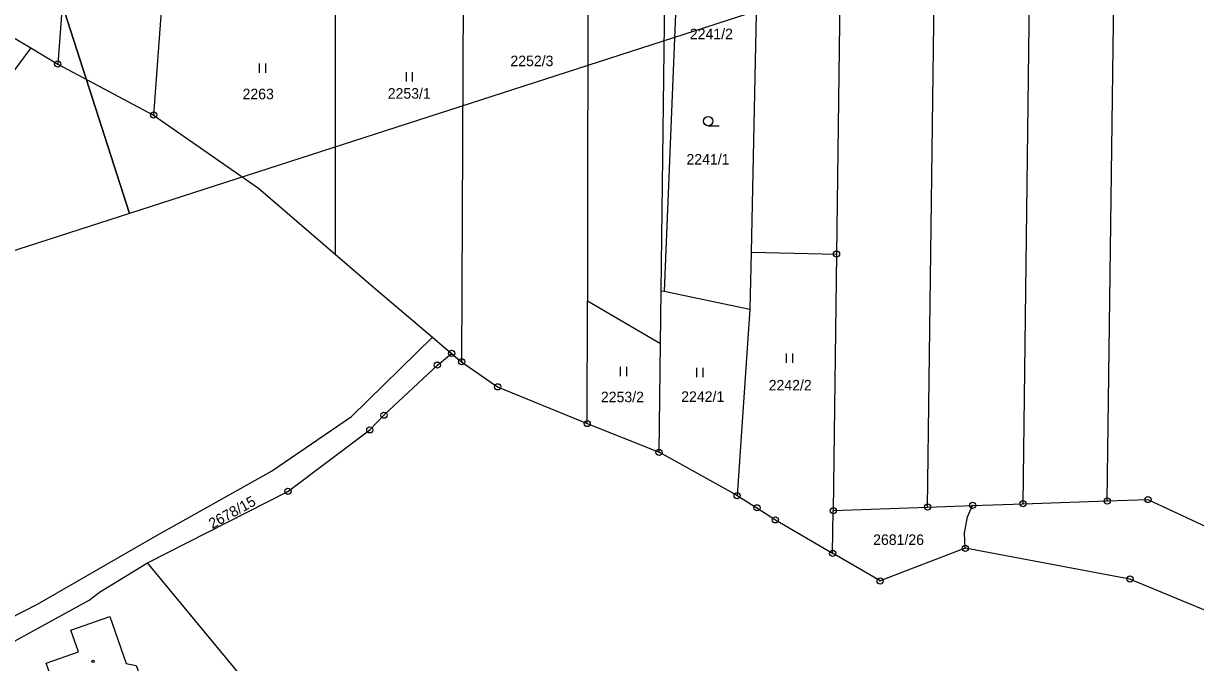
# Model space of a CAD drawing. Extents: x -758836 to -757729, y -1175316 to -1174366.
# Drawn here: x -758289.2 to -758099.9, y -1174936.9 to -1174833.7 of the extents above; entities that cross this region are included whole.
import ezdxf

# ---------------------------------------------------------------- set-up
doc = ezdxf.new("R2010")
doc.units = 0
for name, color, linetype in [('_NOR-pomocná', 7, 'Continuous'), ('Hranice parcel', 7, 'Continuous'), ('Parcelní čísla', 7, 'Continuous'), ('Značky bodu BP', 7, 'Continuous'), ('Značky budov', 7, 'Continuous'), ('Značky kultur', 7, 'Continuous')]:
    doc.layers.add(name, color=color, linetype=linetype)

msp = doc.modelspace()

# ---------------------------------------------------------------- linework, layer by layer
at = {"layer": '_NOR-pomocná'}
for points in [[(-758317.65, -1174723.03), (-758217.71, -1174690.84), (-758172.18, -1174832.19), (-758272.12, -1174864.38)], [(-758417.59, -1174755.22), (-758317.65, -1174723.03), (-758272.12, -1174864.38), (-758372.07, -1174896.57)]]:
    msp.add_lwpolyline(points, close=True, dxfattribs=at)
at = {"layer": 'Hranice parcel'}
for p, q in [((-758127.73, -1174911.25), (-758125.97, -1174774.42)), ((-758114.13, -1174910.8), (-758112.36, -1174774.1)), ((-758156.63, -1174775.13), (-758157.87, -1174870.96)), ((-758143.14, -1174911.79), (-758141.37, -1174774.78)), ((-758266.21, -1174821.26), (-758268.21, -1174848.52)), ((-758186.22, -1174876.87), (-758185.53, -1174823.65)), ((-758183.53, -1174823.59), (-758185.73, -1174876.96)), ((-758170.66, -1174823.2), (-758171.67, -1174870.63)), ((-758238.86, -1174825.45), (-758238.89, -1174870.98)), ((-758218.18, -1174826.63), (-758218.45, -1174888.34)), ((-758288.06, -1174837.68), (-758283.71, -1174840.27)), ((-758283.71, -1174840.27), (-758268.21, -1174848.52)), ((-758171.67, -1174870.63), (-758171.87, -1174879.84)), ((-758171.67, -1174870.63), (-758157.87, -1174870.96)), ((-758157.87, -1174870.96), (-758158.4, -1174912.36)), ((-758198.15, -1174898.31), (-758198.12, -1174878.49)), ((-758198.12, -1174878.49), (-758186.32, -1174885.38)), ((-758186.32, -1174885.38), (-758186.22, -1174876.87)), ((-758186.22, -1174876.87), (-758185.73, -1174876.96)), ((-758185.73, -1174876.96), (-758171.87, -1174879.84)), ((-758171.87, -1174879.84), (-758173.93, -1174909.94)), ((-758223.14, -1174884.37), (-758220.06, -1174886.98)), ((-758186.55, -1174902.95), (-758186.32, -1174885.38)), ((-758220.06, -1174886.98), (-758218.45, -1174888.34)), ((-758198.15, -1174898.31), (-758186.55, -1174902.95)), ((-758173.93, -1174909.94), (-758186.55, -1174902.95)), ((-758127.73, -1174911.25), (-758114.13, -1174910.8)), ((-758158.49, -1174919.25), (-758158.4, -1174912.36)), ((-758158.4, -1174912.36), (-758143.14, -1174911.79)), ((-758143.14, -1174911.79), (-758135.88, -1174911.52)), ((-758135.88, -1174911.52), (-758127.73, -1174911.25))]:
    msp.add_line(p, q, dxfattribs=at)
for points in [[(-758198.02, -1174777.55), (-758198.11, -1174871.18), (-758198.12, -1174878.49)], [(-758279.42, -1174790.47), (-758280.36, -1174800.21), (-758281.37, -1174809.16), (-758283.71, -1174840.27)], [(-758297.37, -1174832.15), (-758289.78, -1174836.66), (-758288.06, -1174837.68)], [(-758288.06, -1174837.68), (-758302.03, -1174856.47), (-758310.72, -1174849.73)], [(-758268.21, -1174848.52), (-758251.29, -1174860.33), (-758238.89, -1174870.98)], [(-758238.89, -1174870.98), (-758232.33, -1174876.61), (-758223.14, -1174884.37)], [(-758302.92, -1174935.57), (-758286.99, -1174927.44), (-758267.9, -1174916.47), (-758249.14, -1174905.98), (-758236.24, -1174897.16), (-758223.14, -1174884.37)], [(-758269.21, -1174920.77), (-758246.51, -1174909.26), (-758233.28, -1174899.33), (-758231, -1174896.96), (-758222.36, -1174888.88), (-758220.06, -1174886.98)], [(-758218.45, -1174888.34), (-758212.63, -1174892.38), (-758198.15, -1174898.31)], [(-758173.93, -1174909.94), (-758170.73, -1174911.91), (-758167.75, -1174913.86), (-758158.49, -1174919.25)], [(-758114.13, -1174910.8), (-758107.54, -1174910.58), (-758080.03, -1174923.36), (-758076.9, -1174924.17)], [(-758137.06, -1174918.45), (-758137.2, -1174915.99), (-758136.71, -1174913.36), (-758135.88, -1174911.52)], [(-758137.06, -1174918.45), (-758150.82, -1174923.72), (-758158.49, -1174919.25)], [(-757919.47, -1174939.02), (-757939.8, -1174930.25), (-757949.26, -1174927.98), (-757957.21, -1174927.28), (-758013.54, -1174927.25), (-758023.59, -1174928.73), (-758047.8, -1174938.11), (-758063.96, -1174936.81), (-758089.79, -1174931.96), (-758110.46, -1174923.41), (-758137.06, -1174918.45)], [(-758297.41, -1174937.08), (-758278.62, -1174926.8), (-758276.96, -1174925.54), (-758269.21, -1174920.77)], [(-758296.01, -1174964.46), (-758247.07, -1174947.51), (-758269.21, -1174920.77)], [(-758271, -1174941.74), (-758282.48, -1174945.75), (-758283.82, -1174941.92), (-758285.42, -1174942.48), (-758286.25, -1174940.1), (-758284.66, -1174939.55), (-758285.55, -1174937), (-758280.36, -1174935.18), (-758281.59, -1174931.68), (-758275.27, -1174929.47), (-758272.62, -1174937.05), (-758271.01, -1174937.37), (-758269.92, -1174940.49), (-758271, -1174941.74)]]:
    msp.add_lwpolyline(points, dxfattribs=at)
at = {"layer": 'Značky bodu BP'}
for centre, radius in [((-758283.71, -1174840.27), 0.5), ((-758283.71, -1174840.27), 0.0303), ((-758268.21, -1174848.52), 0.5), ((-758268.21, -1174848.52), 0.0303), ((-758157.87, -1174870.96), 0.5), ((-758157.87, -1174870.96), 0.0303), ((-758220.06, -1174886.98), 0.5), ((-758220.06, -1174886.98), 0.0303), ((-758218.45, -1174888.34), 0.5), ((-758222.36, -1174888.88), 0.5), ((-758222.36, -1174888.88), 0.0303), ((-758218.45, -1174888.34), 0.0303), ((-758212.63, -1174892.38), 0.5), ((-758212.63, -1174892.38), 0.0303), ((-758231, -1174896.96), 0.5), ((-758231, -1174896.96), 0.0303), ((-758233.28, -1174899.33), 0.5), ((-758233.28, -1174899.33), 0.0303), ((-758198.15, -1174898.31), 0.5), ((-758198.15, -1174898.31), 0.0303), ((-758186.55, -1174902.95), 0.5), ((-758186.55, -1174902.95), 0.0303), ((-758246.51, -1174909.26), 0.5), ((-758246.51, -1174909.26), 0.0303), ((-758173.93, -1174909.94), 0.5), ((-758173.93, -1174909.94), 0.0303), ((-758127.73, -1174911.25), 0.5), ((-758114.13, -1174910.8), 0.5), ((-758114.13, -1174910.8), 0.0303), ((-758107.54, -1174910.58), 0.5), ((-758107.54, -1174910.58), 0.0303), ((-758170.73, -1174911.91), 0.5), ((-758170.73, -1174911.91), 0.0303), ((-758158.4, -1174912.36), 0.5), ((-758158.4, -1174912.36), 0.0303), ((-758143.14, -1174911.79), 0.5), ((-758143.14, -1174911.79), 0.0303), ((-758135.88, -1174911.52), 0.5), ((-758135.88, -1174911.52), 0.0303), ((-758127.73, -1174911.25), 0.0303), ((-758167.75, -1174913.86), 0.5), ((-758167.75, -1174913.86), 0.0303), ((-758137.06, -1174918.45), 0.5), ((-758137.06, -1174918.45), 0.0303), ((-758158.49, -1174919.25), 0.5), ((-758158.49, -1174919.25), 0.0303), ((-758150.82, -1174923.72), 0.5), ((-758150.82, -1174923.72), 0.0303), ((-758110.46, -1174923.41), 0.5), ((-758110.46, -1174923.41), 0.0303)]:
    msp.add_circle(centre, radius, dxfattribs=at)
at = {"layer": 'Značky budov'}
msp.add_circle((-758278.01, -1174936.7), 0.175, dxfattribs=at)
at = {"layer": 'Značky kultur'}
for p, q in [((-758251.08, -1174841.7), (-758251.08, -1174840.2)), ((-758250.08, -1174841.7), (-758250.08, -1174840.2)), ((-758227.36, -1174843.09), (-758227.36, -1174841.59)), ((-758226.36, -1174843.09), (-758226.36, -1174841.59)), ((-758178.59, -1174850.25), (-758176.84, -1174850.25)), ((-758165.95, -1174888.49), (-758165.95, -1174886.99)), ((-758164.95, -1174888.49), (-758164.95, -1174886.99)), ((-758192.77, -1174890.64), (-758192.77, -1174889.14)), ((-758191.77, -1174890.64), (-758191.77, -1174889.14)), ((-758180.43, -1174890.81), (-758180.43, -1174889.31)), ((-758179.43, -1174890.81), (-758179.43, -1174889.31))]:
    msp.add_line(p, q, dxfattribs=at)
msp.add_circle((-758178.59, -1174849.5), 0.75, dxfattribs=at)

# ---------------------------------------------------------------- texts
at = {"layer": 'Parcelní čísla'}
for s, p in [('2241/2', (-758181.56, -1174836.27)), ('2252/3', (-758210.56, -1174840.62)), ('2263', (-758253.84, -1174845.96)), ('2253/1', (-758230.38, -1174845.87)), ('2241/1', (-758182.11, -1174856.5)), ('2242/2', (-758168.83, -1174892.97)), ('2253/2', (-758195.94, -1174894.87)), ('2242/1', (-758182.96, -1174894.81)), ('2681/26', (-758151.95, -1174917.91))]:
    msp.add_text(s, height=1.7, dxfattribs=at).set_placement(p)
msp.add_text('2678/15', height=1.7, rotation=29, dxfattribs=at).set_placement((-758258.72, -1174915.36))

doc.saveas('drawing.dxf')
